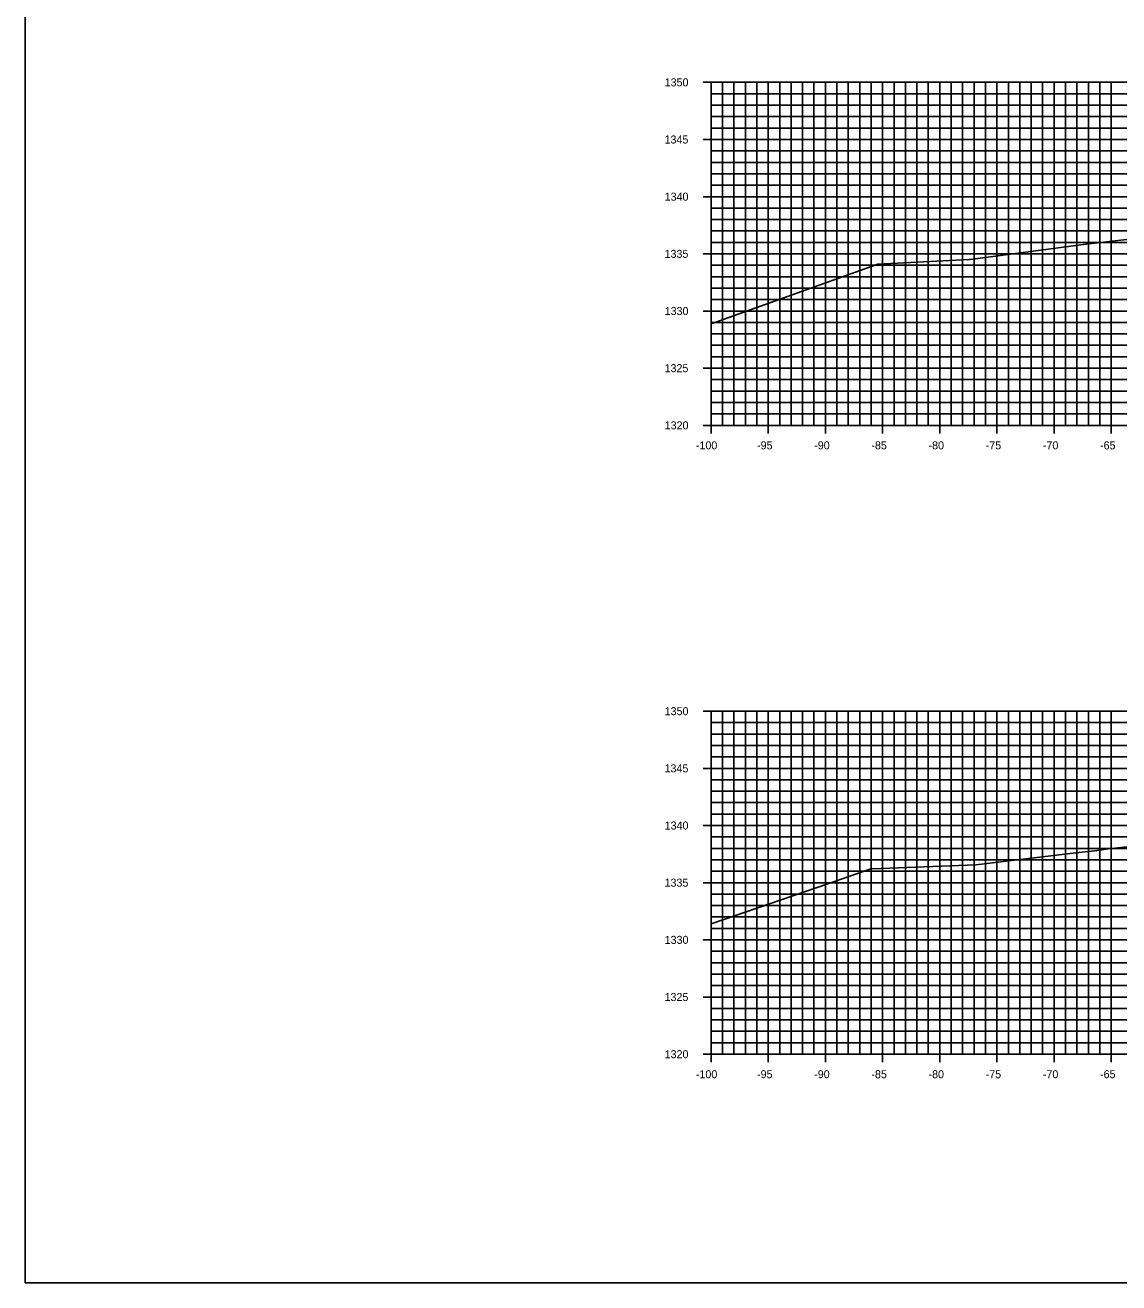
# Model space of a CAD drawing. Extents: x 674939 to 678919, y 750652 to 765176.
# Drawn here: x 678578.5 to 678674.2, y 752992.6 to 753102.6 of the extents above; entities that cross this region are included whole.
import ezdxf

# ---------------------------------------------------------------- set-up
doc = ezdxf.new("R2010")
doc.units = 0
for name, color, linetype in [('R_Axis', 7, 'Continuous'), ('R_Axis Annot', 7, 'Continuous'), ('R_Exist Surface', 7, 'Continuous'), ('R_Grid', 7, 'Continuous'), ('R_No Plot', 7, 'Continuous')]:
    doc.layers.add(name, color=color, linetype=linetype)

msp = doc.modelspace()

# ---------------------------------------------------------------- linework, layer by layer
at = {"layer": 'R_Axis'}
for p, q in [((678637.83, 753097.55), (678639.23, 753097.55)), ((678638.53, 753067.55), (678638.53, 753097.55)), ((678638.53, 753096.55), (678638.88, 753096.55)), ((678638.53, 753095.55), (678638.88, 753095.55)), ((678638.53, 753094.55), (678638.88, 753094.55)), ((678638.53, 753093.55), (678638.88, 753093.55)), ((678637.83, 753092.55), (678639.23, 753092.55)), ((678638.53, 753091.55), (678638.88, 753091.55)), ((678638.53, 753090.55), (678638.88, 753090.55)), ((678638.53, 753089.55), (678638.88, 753089.55)), ((678637.83, 753087.55), (678639.23, 753087.55)), ((678638.53, 753088.55), (678638.88, 753088.55)), ((678638.53, 753086.55), (678638.88, 753086.55)), ((678638.53, 753085.55), (678638.88, 753085.55)), ((678638.53, 753084.55), (678638.88, 753084.55)), ((678638.53, 753083.55), (678638.88, 753083.55)), ((678637.83, 753082.55), (678639.23, 753082.55)), ((678638.53, 753081.55), (678638.88, 753081.55)), ((678638.53, 753080.55), (678638.88, 753080.55)), ((678638.53, 753079.55), (678638.88, 753079.55)), ((678638.53, 753078.55), (678638.88, 753078.55)), ((678637.83, 753077.55), (678639.23, 753077.55)), ((678638.53, 753076.55), (678638.88, 753076.55)), ((678638.53, 753075.55), (678638.88, 753075.55)), ((678638.53, 753074.55), (678638.88, 753074.55)), ((678638.53, 753073.55), (678638.88, 753073.55)), ((678637.83, 753072.55), (678639.23, 753072.55)), ((678638.53, 753071.55), (678638.88, 753071.55)), ((678638.53, 753070.55), (678638.88, 753070.55)), ((678638.53, 753069.55), (678638.88, 753069.55)), ((678638.53, 753068.55), (678638.88, 753068.55)), ((678638.53, 753066.85), (678638.53, 753068.25)), ((678643.53, 753066.85), (678643.53, 753068.25)), ((678648.53, 753066.85), (678648.53, 753068.25)), ((678653.53, 753066.85), (678653.53, 753068.25)), ((678658.53, 753066.85), (678658.53, 753068.25)), ((678663.53, 753066.85), (678663.53, 753068.25)), ((678668.53, 753066.85), (678668.53, 753068.25)), ((678673.53, 753066.85), (678673.53, 753068.25)), ((678637.83, 753067.55), (678639.23, 753067.55)), ((678638.53, 753067.55), (678838.53, 753067.55)), ((678637.83, 753042.55), (678639.23, 753042.55)), ((678638.53, 753012.55), (678638.53, 753042.55)), ((678638.53, 753041.55), (678638.88, 753041.55)), ((678638.53, 753040.55), (678638.88, 753040.55)), ((678638.53, 753039.55), (678638.88, 753039.55)), ((678638.53, 753038.55), (678638.88, 753038.55)), ((678637.83, 753037.55), (678639.23, 753037.55)), ((678638.53, 753036.55), (678638.88, 753036.55)), ((678638.53, 753035.55), (678638.88, 753035.55)), ((678638.53, 753034.55), (678638.88, 753034.55)), ((678637.83, 753032.55), (678639.23, 753032.55)), ((678638.53, 753033.55), (678638.88, 753033.55)), ((678638.53, 753031.55), (678638.88, 753031.55)), ((678638.53, 753030.55), (678638.88, 753030.55)), ((678638.53, 753029.55), (678638.88, 753029.55)), ((678638.53, 753028.55), (678638.88, 753028.55)), ((678637.83, 753027.55), (678639.23, 753027.55)), ((678638.53, 753026.55), (678638.88, 753026.55)), ((678638.53, 753025.55), (678638.88, 753025.55)), ((678638.53, 753024.55), (678638.88, 753024.55)), ((678638.53, 753023.55), (678638.88, 753023.55)), ((678637.83, 753022.55), (678639.23, 753022.55)), ((678638.53, 753021.55), (678638.88, 753021.55)), ((678638.53, 753020.55), (678638.88, 753020.55)), ((678638.53, 753019.55), (678638.88, 753019.55)), ((678638.53, 753018.55), (678638.88, 753018.55)), ((678637.83, 753017.55), (678639.23, 753017.55)), ((678638.53, 753016.55), (678638.88, 753016.55)), ((678638.53, 753015.55), (678638.88, 753015.55)), ((678638.53, 753014.55), (678638.88, 753014.55)), ((678638.53, 753013.55), (678638.88, 753013.55)), ((678638.53, 753011.85), (678638.53, 753013.25)), ((678643.53, 753011.85), (678643.53, 753013.25)), ((678648.53, 753011.85), (678648.53, 753013.25)), ((678653.53, 753011.85), (678653.53, 753013.25)), ((678658.53, 753011.85), (678658.53, 753013.25)), ((678663.53, 753011.85), (678663.53, 753013.25)), ((678668.53, 753011.85), (678668.53, 753013.25)), ((678673.53, 753011.85), (678673.53, 753013.25)), ((678637.83, 753012.55), (678639.23, 753012.55)), ((678638.53, 753012.55), (678838.53, 753012.55))]:
    msp.add_line(p, q, dxfattribs=at)
at = {"layer": 'R_Exist Surface'}
for points in [[(678638.53, 753076.42), (678653.12, 753081.65), (678661.11, 753082.04), (678661.19, 753082.04), (678671.54, 753083.43), (678671.75, 753083.45), (678671.83, 753083.46), (678675.4, 753083.87)], [(678638.53, 753023.94), (678648.84, 753027.49), (678652.51, 753028.76), (678653.41, 753028.79), (678661.69, 753029.11), (678670.43, 753030.15), (678672.07, 753030.35), (678673.29, 753030.5), (678675.44, 753030.74)]]:
    msp.add_lwpolyline(points, dxfattribs=at)
at = {"layer": 'R_Grid'}
for p, q in [((678638.53, 753097.55), (678838.53, 753097.55)), ((678638.53, 753067.55), (678638.53, 753097.55)), ((678639.53, 753067.55), (678639.53, 753097.55)), ((678640.53, 753067.55), (678640.53, 753097.55)), ((678641.53, 753067.55), (678641.53, 753097.55)), ((678642.53, 753067.55), (678642.53, 753097.55)), ((678643.53, 753067.55), (678643.53, 753097.55)), ((678644.53, 753067.55), (678644.53, 753097.55)), ((678645.53, 753067.55), (678645.53, 753097.55)), ((678646.53, 753067.55), (678646.53, 753097.55)), ((678647.53, 753067.55), (678647.53, 753097.55)), ((678648.53, 753067.55), (678648.53, 753097.55)), ((678649.53, 753067.55), (678649.53, 753097.55)), ((678650.53, 753067.55), (678650.53, 753097.55)), ((678651.53, 753067.55), (678651.53, 753097.55)), ((678652.53, 753067.55), (678652.53, 753097.55)), ((678653.53, 753067.55), (678653.53, 753097.55)), ((678654.53, 753067.55), (678654.53, 753097.55)), ((678655.53, 753067.55), (678655.53, 753097.55)), ((678656.53, 753067.55), (678656.53, 753097.55)), ((678657.53, 753067.55), (678657.53, 753097.55)), ((678658.53, 753067.55), (678658.53, 753097.55)), ((678659.53, 753067.55), (678659.53, 753097.55)), ((678660.53, 753067.55), (678660.53, 753097.55)), ((678661.53, 753067.55), (678661.53, 753097.55)), ((678662.53, 753067.55), (678662.53, 753097.55)), ((678663.53, 753067.55), (678663.53, 753097.55)), ((678664.53, 753067.55), (678664.53, 753097.55)), ((678665.53, 753067.55), (678665.53, 753097.55)), ((678666.53, 753067.55), (678666.53, 753097.55)), ((678667.53, 753067.55), (678667.53, 753097.55)), ((678668.53, 753067.55), (678668.53, 753097.55)), ((678669.53, 753067.55), (678669.53, 753097.55)), ((678670.53, 753067.55), (678670.53, 753097.55)), ((678671.53, 753067.55), (678671.53, 753097.55)), ((678672.53, 753067.55), (678672.53, 753097.55)), ((678673.53, 753067.55), (678673.53, 753097.55)), ((678638.53, 753096.55), (678838.53, 753096.55)), ((678638.53, 753095.55), (678838.53, 753095.55)), ((678638.53, 753094.55), (678838.53, 753094.55)), ((678638.53, 753093.55), (678838.53, 753093.55)), ((678638.53, 753092.55), (678838.53, 753092.55)), ((678638.53, 753091.55), (678838.53, 753091.55)), ((678638.53, 753090.55), (678838.53, 753090.55)), ((678638.53, 753089.55), (678838.53, 753089.55)), ((678638.53, 753088.55), (678838.53, 753088.55)), ((678638.53, 753087.55), (678838.53, 753087.55)), ((678638.53, 753086.55), (678838.53, 753086.55)), ((678638.53, 753085.55), (678838.53, 753085.55)), ((678638.53, 753084.55), (678838.53, 753084.55)), ((678638.53, 753083.55), (678838.53, 753083.55)), ((678638.53, 753082.55), (678838.53, 753082.55)), ((678638.53, 753081.55), (678838.53, 753081.55)), ((678638.53, 753080.55), (678838.53, 753080.55)), ((678638.53, 753079.55), (678838.53, 753079.55)), ((678638.53, 753078.55), (678838.53, 753078.55)), ((678638.53, 753077.55), (678838.53, 753077.55)), ((678638.53, 753076.55), (678838.53, 753076.55)), ((678638.53, 753075.55), (678838.53, 753075.55)), ((678638.53, 753074.55), (678838.53, 753074.55)), ((678638.53, 753073.55), (678838.53, 753073.55)), ((678638.53, 753072.55), (678838.53, 753072.55)), ((678638.53, 753071.55), (678838.53, 753071.55)), ((678638.53, 753070.55), (678838.53, 753070.55)), ((678638.53, 753069.55), (678838.53, 753069.55)), ((678638.53, 753068.55), (678838.53, 753068.55)), ((678638.53, 753067.55), (678838.53, 753067.55)), ((678638.53, 753042.55), (678838.53, 753042.55)), ((678638.53, 753012.55), (678638.53, 753042.55)), ((678639.53, 753012.55), (678639.53, 753042.55)), ((678640.53, 753012.55), (678640.53, 753042.55)), ((678641.53, 753012.55), (678641.53, 753042.55)), ((678642.53, 753012.55), (678642.53, 753042.55)), ((678643.53, 753012.55), (678643.53, 753042.55)), ((678644.53, 753012.55), (678644.53, 753042.55)), ((678645.53, 753012.55), (678645.53, 753042.55)), ((678646.53, 753012.55), (678646.53, 753042.55)), ((678647.53, 753012.55), (678647.53, 753042.55)), ((678648.53, 753012.55), (678648.53, 753042.55)), ((678649.53, 753012.55), (678649.53, 753042.55)), ((678650.53, 753012.55), (678650.53, 753042.55)), ((678651.53, 753012.55), (678651.53, 753042.55)), ((678652.53, 753012.55), (678652.53, 753042.55)), ((678653.53, 753012.55), (678653.53, 753042.55)), ((678654.53, 753012.55), (678654.53, 753042.55)), ((678655.53, 753012.55), (678655.53, 753042.55)), ((678656.53, 753012.55), (678656.53, 753042.55)), ((678657.53, 753012.55), (678657.53, 753042.55)), ((678658.53, 753012.55), (678658.53, 753042.55)), ((678659.53, 753012.55), (678659.53, 753042.55)), ((678660.53, 753012.55), (678660.53, 753042.55)), ((678661.53, 753012.55), (678661.53, 753042.55)), ((678662.53, 753012.55), (678662.53, 753042.55)), ((678663.53, 753012.55), (678663.53, 753042.55)), ((678664.53, 753012.55), (678664.53, 753042.55)), ((678665.53, 753012.55), (678665.53, 753042.55)), ((678666.53, 753012.55), (678666.53, 753042.55)), ((678667.53, 753012.55), (678667.53, 753042.55)), ((678668.53, 753012.55), (678668.53, 753042.55)), ((678669.53, 753012.55), (678669.53, 753042.55)), ((678670.53, 753012.55), (678670.53, 753042.55)), ((678671.53, 753012.55), (678671.53, 753042.55)), ((678672.53, 753012.55), (678672.53, 753042.55)), ((678673.53, 753012.55), (678673.53, 753042.55)), ((678638.53, 753041.55), (678838.53, 753041.55)), ((678638.53, 753040.55), (678838.53, 753040.55)), ((678638.53, 753039.55), (678838.53, 753039.55)), ((678638.53, 753038.55), (678838.53, 753038.55)), ((678638.53, 753037.55), (678838.53, 753037.55)), ((678638.53, 753036.55), (678838.53, 753036.55)), ((678638.53, 753035.55), (678838.53, 753035.55)), ((678638.53, 753034.55), (678838.53, 753034.55)), ((678638.53, 753033.55), (678838.53, 753033.55)), ((678638.53, 753032.55), (678838.53, 753032.55)), ((678638.53, 753031.55), (678838.53, 753031.55)), ((678638.53, 753030.55), (678838.53, 753030.55)), ((678638.53, 753029.55), (678838.53, 753029.55)), ((678638.53, 753028.55), (678838.53, 753028.55)), ((678638.53, 753027.55), (678838.53, 753027.55)), ((678638.53, 753026.55), (678838.53, 753026.55)), ((678638.53, 753025.55), (678838.53, 753025.55)), ((678638.53, 753024.55), (678838.53, 753024.55)), ((678638.53, 753023.55), (678838.53, 753023.55)), ((678638.53, 753022.55), (678838.53, 753022.55)), ((678638.53, 753021.55), (678838.53, 753021.55)), ((678638.53, 753020.55), (678838.53, 753020.55)), ((678638.53, 753019.55), (678838.53, 753019.55)), ((678638.53, 753018.55), (678838.53, 753018.55)), ((678638.53, 753017.55), (678838.53, 753017.55)), ((678638.53, 753016.55), (678838.53, 753016.55)), ((678638.53, 753015.55), (678838.53, 753015.55)), ((678638.53, 753014.55), (678838.53, 753014.55)), ((678638.53, 753013.55), (678838.53, 753013.55)), ((678638.53, 753012.55), (678838.53, 753012.55))]:
    msp.add_line(p, q, dxfattribs=at)
at = {"layer": 'R_No Plot'}
msp.add_lwpolyline([(678578.53, 752992.55), (678918.53, 752992.55), (678918.53, 753212.55), (678578.53, 753212.55)], close=True, dxfattribs=at)

# ---------------------------------------------------------------- texts
at = {"layer": 'R_Axis Annot'}
for s, p in [('1350', (678634.47, 753097.2)), ('1345', (678634.46, 753092.2)), ('1340', (678634.47, 753087.2)), ('1335', (678634.46, 753082.2)), ('1330', (678634.47, 753077.2)), ('1325', (678634.46, 753072.2)), ('1320', (678634.47, 753067.2)), ('-100', (678637.2, 753065.45)), ('-95', (678642.55, 753065.45)), ('-90', (678647.55, 753065.45)), ('-85', (678652.55, 753065.45)), ('-80', (678657.55, 753065.45)), ('-75', (678662.55, 753065.45)), ('-70', (678667.55, 753065.45)), ('-65', (678672.55, 753065.45)), ('1350', (678634.47, 753042.2)), ('1345', (678634.46, 753037.2)), ('1340', (678634.47, 753032.2)), ('1335', (678634.46, 753027.2)), ('1330', (678634.47, 753022.2)), ('1325', (678634.46, 753017.2)), ('1320', (678634.47, 753012.2)), ('-100', (678637.2, 753010.45)), ('-95', (678642.55, 753010.45)), ('-90', (678647.55, 753010.45)), ('-85', (678652.55, 753010.45)), ('-80', (678657.55, 753010.45)), ('-75', (678662.55, 753010.45)), ('-70', (678667.55, 753010.45)), ('-65', (678672.55, 753010.45))]:
    msp.add_text(s, height=0.7, dxfattribs=at).set_placement(p)

doc.saveas('drawing.dxf')
